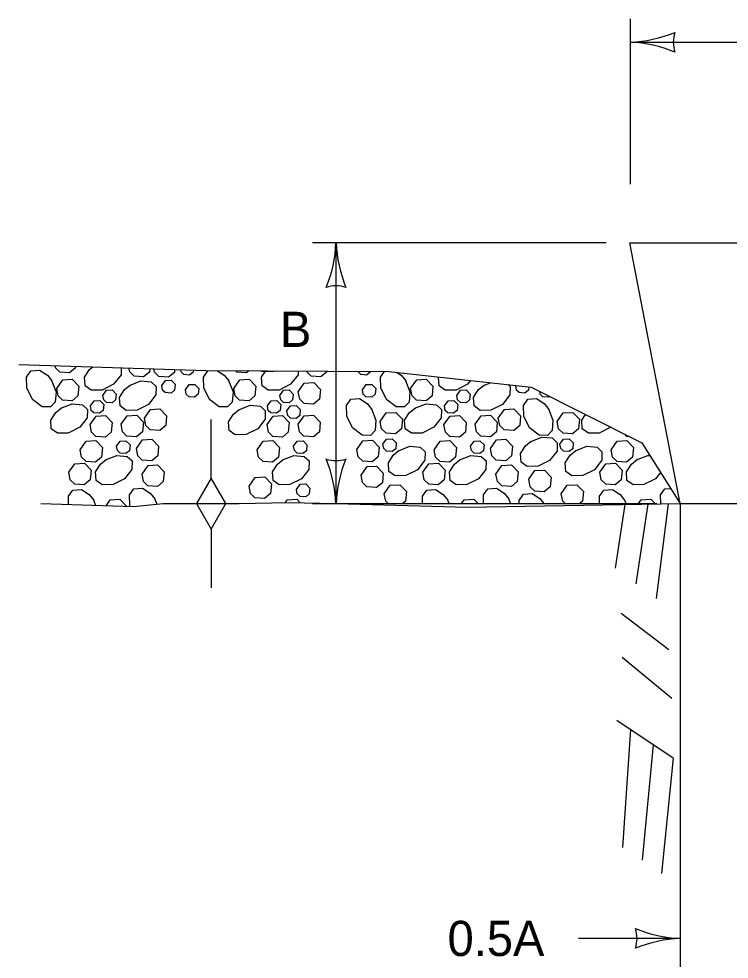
# Model space of a CAD drawing. Extents: x 49991.4 to 50021, y 49987.6 to 50011.4.
# Drawn here: x 50008.562 to 50009.772, y 49996.429 to 49998.032 of the extents above; entities that cross this region are included whole.
import ezdxf

# ---------------------------------------------------------------- set-up
doc = ezdxf.new("R2010")
doc.units = 0
for name, color, linetype in [('Level 1', 7, 'Continuous'), ('Level 2', 7, 'Continuous'), ('Level 3', 7, 'Continuous')]:
    doc.layers.add(name, color=color, linetype=linetype)

msp = doc.modelspace()

# ---------------------------------------------------------------- linework, layer by layer
at = {"layer": 'Level 1'}
for p, q in [((50009.6885, 49997.2058), (50009.6025, 49997.6503)), ((50009.6034, 49997.6503), (50010.4318, 49997.6503)), ((50009.6425, 49997.6503), (50010.4321, 49997.6503)), ((50009.3536, 49997.4073), (50009.3652, 49997.4119)), ((50009.4084, 49997.407), (50009.4084, 49997.4071)), ((50008.8892, 49997.2491), (50008.8892, 49997.3491)), ((50008.8892, 49997.2491), (50008.8642, 49997.2058)), ((50008.9142, 49997.2058), (50008.8892, 49997.2491)), ((50008.6888, 49997.2123), (50008.6925, 49997.2029)), ((50008.7929, 49997.2148), (50008.7969, 49997.2047)), ((50008.8648, 49997.2047), (50008.8892, 49997.1625)), ((50008.8892, 49997.1625), (50008.9142, 49997.2058)), ((50009.0622, 49997.2058), (50009.6485, 49997.2058)), ((50009.2919, 49997.2123), (50009.2945, 49997.2058)), ((50009.396, 49997.2148), (50009.3996, 49997.2058)), ((50009.5945, 49997.2043), (50009.578, 49997.0956)), ((50009.5934, 49997.2123), (50009.596, 49997.2058)), ((50009.6334, 49997.2049), (50009.6128, 49997.0692)), ((50009.668, 49997.2055), (50009.6475, 49997.0442)), ((50009.6885, 49997.2058), (50009.6885, 49994.0392)), ((50009.6885, 49997.2058), (50010.3553, 49997.2058)), ((50008.8892, 49997.1625), (50008.8892, 49997.0625)), ((50009.6691, 49996.9565), (50009.5881, 49997.0186)), ((50009.6743, 49996.8736), (50009.5896, 49996.9437)), ((50009.6768, 49996.7719), (50009.5805, 49996.8365)), ((50009.604, 49996.8207), (50009.5902, 49996.62)), ((50009.6427, 49996.7948), (50009.6239, 49996.598)), ((50009.6768, 49996.7719), (50009.6565, 49996.5756))]:
    msp.add_line(p, q, dxfattribs=at)
for points in [[(50008.5617, 49997.443), (50008.881, 49997.4327), (50009.1922, 49997.431), (50009.4347, 49997.4042), (50009.6233, 49997.3093), (50009.6885, 49997.2058)], [(50008.6175, 49997.4157), (50008.6251, 49997.3965), (50008.6236, 49997.3789), (50008.6156, 49997.3705), (50008.6013, 49997.3708), (50008.5851, 49997.3835), (50008.5753, 49997.4031), (50008.575, 49997.4216), (50008.5824, 49997.432), (50008.5971, 49997.433), (50008.6103, 49997.4246), (50008.618, 49997.4149)], [(50008.6582, 49997.4399), (50008.658, 49997.4373), (50008.6479, 49997.4289), (50008.6317, 49997.4301), (50008.6241, 49997.4374), (50008.6234, 49997.441)], [(50008.7361, 49997.4374), (50008.7359, 49997.4254), (50008.7232, 49997.4092), (50008.7036, 49997.3993), (50008.6851, 49997.399), (50008.6747, 49997.4064), (50008.6737, 49997.4212), (50008.6821, 49997.4343), (50008.6879, 49997.4389)], [(50008.7851, 49997.4358), (50008.7845, 49997.4301), (50008.7744, 49997.4217), (50008.7583, 49997.4229), (50008.7507, 49997.4302), (50008.7494, 49997.437)], [(50008.8272, 49997.4344), (50008.8267, 49997.4295), (50008.8166, 49997.4211), (50008.8004, 49997.4222), (50008.7928, 49997.4296), (50008.7917, 49997.4356)], [(50008.8591, 49997.4334), (50008.8588, 49997.4301), (50008.8527, 49997.425), (50008.843, 49997.4258), (50008.8384, 49997.4302), (50008.8377, 49997.4341)], [(50008.9191, 49997.4157), (50008.9267, 49997.3965), (50008.9251, 49997.3789), (50008.9172, 49997.3705), (50008.9029, 49997.3708), (50008.8867, 49997.3835), (50008.8769, 49997.4031), (50008.8765, 49997.4216), (50008.8839, 49997.432), (50008.893, 49997.4326)], [(50008.8993, 49997.4326), (50008.9118, 49997.4246), (50008.9196, 49997.4149)], [(50008.9535, 49997.4323), (50008.9494, 49997.4289), (50008.9333, 49997.4301), (50008.9309, 49997.4324)], [(50008.9738, 49997.4322), (50008.9757, 49997.4318), (50008.9816, 49997.4318), (50008.99, 49997.4314), (50008.9961, 49997.4314), (50009.0011, 49997.432)], [(50009.0376, 49997.4318), (50009.0375, 49997.4254), (50009.0248, 49997.4092), (50009.0051, 49997.3993), (50008.9867, 49997.399), (50008.9762, 49997.4064), (50008.9753, 49997.4212), (50008.9823, 49997.4321)], [(50009.0862, 49997.4316), (50009.0861, 49997.4301), (50009.076, 49997.4217), (50009.0598, 49997.4229), (50009.0522, 49997.4302), (50009.0519, 49997.4318)], [(50009.1604, 49997.4312), (50009.1603, 49997.4301), (50009.1543, 49997.425), (50009.1446, 49997.4258), (50009.14, 49997.4302), (50009.1398, 49997.4313)], [(50009.2206, 49997.4157), (50009.2282, 49997.3965), (50009.2267, 49997.3789), (50009.2187, 49997.3705), (50009.2045, 49997.3708), (50009.1882, 49997.3835), (50009.1784, 49997.4031), (50009.1781, 49997.4216), (50009.1848, 49997.4311)], [(50009.2056, 49997.4295), (50009.2134, 49997.4246), (50009.2211, 49997.4149)], [(50008.6262, 49997.4022), (50008.6365, 49997.4167), (50008.6528, 49997.4177), (50008.6642, 49997.4059), (50008.6625, 49997.3894), (50008.6524, 49997.381), (50008.6363, 49997.3821), (50008.6287, 49997.3895), (50008.6262, 49997.4022)], [(50008.7505, 49997.4073), (50008.7697, 49997.4149), (50008.7873, 49997.4134), (50008.7957, 49997.4054), (50008.7954, 49997.3912), (50008.7827, 49997.3749), (50008.7631, 49997.3651), (50008.7446, 49997.3648), (50008.7341, 49997.3722), (50008.7332, 49997.3869), (50008.7416, 49997.4001), (50008.7513, 49997.4078)], [(50008.8052, 49997.407), (50008.8114, 49997.4158), (50008.8212, 49997.4163), (50008.828, 49997.4093), (50008.827, 49997.3993), (50008.821, 49997.3943), (50008.8113, 49997.395), (50008.8067, 49997.3994), (50008.8053, 49997.407)], [(50008.9278, 49997.4022), (50008.938, 49997.4167), (50008.9544, 49997.4177), (50008.9657, 49997.4059), (50008.9641, 49997.3894), (50008.954, 49997.381), (50008.9378, 49997.3821), (50008.9302, 49997.3895), (50008.9278, 49997.4022)], [(50009.0378, 49997.3966), (50009.0481, 49997.4112), (50009.0644, 49997.4121), (50009.0758, 49997.4003), (50009.0741, 49997.3838), (50009.064, 49997.3754), (50009.0479, 49997.3765), (50009.0403, 49997.3839), (50009.0378, 49997.3966)], [(50009.2293, 49997.4022), (50009.2396, 49997.4167), (50009.2559, 49997.4177), (50009.2673, 49997.4059), (50009.2657, 49997.3894), (50009.2556, 49997.381), (50009.2394, 49997.3821), (50009.2318, 49997.3895), (50009.2293, 49997.4022)], [(50009.3314, 49997.4156), (50009.3263, 49997.4092), (50009.3067, 49997.3993), (50009.2882, 49997.399), (50009.2778, 49997.4064), (50009.2768, 49997.4212), (50009.2771, 49997.4216)], [(50008.7048, 49997.3902), (50008.711, 49997.399), (50008.7208, 49997.3995), (50008.7276, 49997.3924), (50008.7266, 49997.3825), (50008.7206, 49997.3775), (50008.7109, 49997.3782), (50008.7063, 49997.3826), (50008.7048, 49997.3902)], [(50008.8456, 49997.3998), (50008.8518, 49997.4086), (50008.8616, 49997.4091), (50008.8684, 49997.402), (50008.8674, 49997.3921), (50008.8613, 49997.3871), (50008.8517, 49997.3878), (50008.8471, 49997.3922), (50008.8456, 49997.3998)], [(50009.0064, 49997.3902), (50009.0125, 49997.399), (50009.0224, 49997.3995), (50009.0292, 49997.3924), (50009.0282, 49997.3825), (50009.0221, 49997.3775), (50009.0124, 49997.3782), (50009.0079, 49997.3826), (50009.0064, 49997.3902)], [(50009.1472, 49997.3998), (50009.1533, 49997.4086), (50009.1631, 49997.4091), (50009.1699, 49997.402), (50009.169, 49997.3921), (50009.1629, 49997.3871), (50009.1532, 49997.3878), (50009.1486, 49997.3922), (50009.1472, 49997.3998)], [(50009.3079, 49997.3902), (50009.3141, 49997.399), (50009.3239, 49997.3995), (50009.3307, 49997.3924), (50009.3297, 49997.3825), (50009.3237, 49997.3775), (50009.314, 49997.3782), (50009.3094, 49997.3826), (50009.308, 49997.3902)], [(50009.3955, 49997.4086), (50009.3988, 49997.4054), (50009.3985, 49997.3912), (50009.3858, 49997.3749), (50009.3662, 49997.3651), (50009.3477, 49997.3648), (50009.3373, 49997.3722), (50009.3363, 49997.3869), (50009.3447, 49997.4001), (50009.3544, 49997.4078)], [(50009.4307, 49997.4047), (50009.4302, 49997.3993), (50009.4241, 49997.3943), (50009.4144, 49997.395), (50009.4098, 49997.3994), (50009.4084, 49997.407)], [(50009.4661, 49997.3884), (50009.4645, 49997.3871), (50009.4548, 49997.3878), (50009.4502, 49997.3922), (50009.4493, 49997.3969)], [(50008.6837, 49997.3724), (50008.6899, 49997.3812), (50008.6997, 49997.3817), (50008.7065, 49997.3747), (50008.7055, 49997.3648), (50008.6994, 49997.3597), (50008.6897, 49997.3604), (50008.6852, 49997.3648), (50008.6837, 49997.3724)], [(50008.9853, 49997.3724), (50008.9914, 49997.3812), (50009.0012, 49997.3817), (50009.008, 49997.3747), (50009.0071, 49997.3648), (50009.001, 49997.3597), (50008.9913, 49997.3604), (50008.9867, 49997.3648), (50008.9853, 49997.3724)], [(50009.1626, 49997.3673), (50009.1702, 49997.3481), (50009.1687, 49997.3305), (50009.1608, 49997.3222), (50009.1465, 49997.3224), (50009.1302, 49997.3351), (50009.1204, 49997.3548), (50009.1201, 49997.3733), (50009.1275, 49997.3837), (50009.1422, 49997.3847), (50009.1554, 49997.3762), (50009.1631, 49997.3665)], [(50009.2868, 49997.3724), (50009.293, 49997.3812), (50009.3028, 49997.3817), (50009.3096, 49997.3747), (50009.3086, 49997.3648), (50009.3025, 49997.3597), (50009.2929, 49997.3604), (50009.2883, 49997.3648), (50009.2868, 49997.3724)], [(50009.4642, 49997.3673), (50009.4718, 49997.3481), (50009.4703, 49997.3305), (50009.4623, 49997.3222), (50009.448, 49997.3224), (50009.4318, 49997.3351), (50009.422, 49997.3548), (50009.4217, 49997.3733), (50009.4291, 49997.3837), (50009.4438, 49997.3847), (50009.457, 49997.3762), (50009.4647, 49997.3665)], [(50008.6334, 49997.3683), (50008.6526, 49997.3759), (50008.6702, 49997.3744), (50008.6785, 49997.3664), (50008.6783, 49997.3521), (50008.6656, 49997.3359), (50008.6459, 49997.3261), (50008.6274, 49997.3257), (50008.617, 49997.3331), (50008.616, 49997.3479), (50008.6245, 49997.361), (50008.6342, 49997.3688)], [(50008.7756, 49997.3517), (50008.7859, 49997.3663), (50008.8022, 49997.3672), (50008.8136, 49997.3554), (50008.8119, 49997.3389), (50008.8018, 49997.3305), (50008.7857, 49997.3317), (50008.7781, 49997.339), (50008.7756, 49997.3517)], [(50008.9365, 49997.3658), (50008.9557, 49997.3734), (50008.9733, 49997.3718), (50008.9816, 49997.3639), (50008.9814, 49997.3496), (50008.9687, 49997.3334), (50008.949, 49997.3235), (50008.9305, 49997.3232), (50008.9201, 49997.3306), (50008.9191, 49997.3453), (50008.9276, 49997.3585), (50008.9373, 49997.3662)], [(50009.0185, 49997.3637), (50009.0246, 49997.3725), (50009.0345, 49997.3731), (50009.0413, 49997.366), (50009.0403, 49997.3561), (50009.0342, 49997.351), (50009.0245, 49997.3517), (50009.02, 49997.3561), (50009.0185, 49997.3637)], [(50009.2365, 49997.3683), (50009.2557, 49997.3759), (50009.2733, 49997.3744), (50009.2816, 49997.3664), (50009.2814, 49997.3521), (50009.2687, 49997.3359), (50009.249, 49997.3261), (50009.2305, 49997.3257), (50009.2201, 49997.3331), (50009.2191, 49997.3479), (50009.2276, 49997.361), (50009.2373, 49997.3688)], [(50009.3787, 49997.3517), (50009.389, 49997.3663), (50009.4053, 49997.3672), (50009.4167, 49997.3554), (50009.4151, 49997.3389), (50009.4049, 49997.3305), (50009.3888, 49997.3317), (50009.3812, 49997.339), (50009.3787, 49997.3517)], [(50008.683, 49997.3404), (50008.6933, 49997.355), (50008.7096, 49997.3559), (50008.721, 49997.3441), (50008.7193, 49997.3276), (50008.7092, 49997.3192), (50008.6931, 49997.3204), (50008.6855, 49997.3277), (50008.683, 49997.3404)], [(50008.7359, 49997.341), (50008.7461, 49997.3556), (50008.7625, 49997.3565), (50008.7739, 49997.3447), (50008.7722, 49997.3282), (50008.7621, 49997.3198), (50008.7459, 49997.321), (50008.7384, 49997.3283), (50008.7359, 49997.341)], [(50008.9846, 49997.3404), (50008.9948, 49997.355), (50009.0112, 49997.3559), (50009.0225, 49997.3441), (50009.0209, 49997.3276), (50009.0108, 49997.3192), (50008.9946, 49997.3204), (50008.987, 49997.3277), (50008.9846, 49997.3404)], [(50009.0374, 49997.341), (50009.0477, 49997.3556), (50009.064, 49997.3565), (50009.0754, 49997.3447), (50009.0738, 49997.3282), (50009.0637, 49997.3198), (50009.0475, 49997.321), (50009.0399, 49997.3283), (50009.0374, 49997.341)], [(50009.1774, 49997.3458), (50009.1877, 49997.3604), (50009.204, 49997.3613), (50009.2154, 49997.3495), (50009.2137, 49997.333), (50009.2036, 49997.3246), (50009.1875, 49997.3258), (50009.1799, 49997.3331), (50009.1774, 49997.3458)], [(50009.2861, 49997.3404), (50009.2964, 49997.355), (50009.3127, 49997.3559), (50009.3241, 49997.3441), (50009.3225, 49997.3276), (50009.3124, 49997.3192), (50009.2962, 49997.3204), (50009.2886, 49997.3277), (50009.2861, 49997.3404)], [(50009.339, 49997.341), (50009.3492, 49997.3556), (50009.3656, 49997.3565), (50009.377, 49997.3447), (50009.3753, 49997.3282), (50009.3652, 49997.3198), (50009.3491, 49997.321), (50009.3415, 49997.3283), (50009.339, 49997.341)], [(50009.479, 49997.3458), (50009.4892, 49997.3604), (50009.5056, 49997.3613), (50009.5169, 49997.3495), (50009.5153, 49997.333), (50009.5052, 49997.3246), (50009.489, 49997.3258), (50009.4814, 49997.3331), (50009.479, 49997.3458)], [(50009.5703, 49997.336), (50009.5702, 49997.3359), (50009.5506, 49997.3261), (50009.5321, 49997.3257), (50009.5217, 49997.3331), (50009.5207, 49997.3479), (50009.527, 49997.3577)], [(50009.1821, 49997.3071), (50009.1882, 49997.3158), (50009.198, 49997.3164), (50009.2049, 49997.3093), (50009.2039, 49997.2994), (50009.1978, 49997.2944), (50009.1881, 49997.2951), (50009.1836, 49997.2995), (50009.1821, 49997.3071)], [(50009.4338, 49997.3116), (50009.453, 49997.3192), (50009.4706, 49997.3177), (50009.479, 49997.3097), (50009.4787, 49997.2954), (50009.466, 49997.2792), (50009.4464, 49997.2694), (50009.4279, 49997.2691), (50009.4175, 49997.2765), (50009.4165, 49997.2912), (50009.4249, 49997.3044), (50009.4346, 49997.3121)], [(50009.4836, 49997.3071), (50009.4898, 49997.3158), (50009.4996, 49997.3164), (50009.5064, 49997.3093), (50009.5054, 49997.2994), (50009.4994, 49997.2944), (50009.4897, 49997.2951), (50009.4851, 49997.2995), (50009.4836, 49997.3071)], [(50009.6018, 49997.3201), (50009.5978, 49997.3204), (50009.594, 49997.324)], [(50008.6662, 49997.2977), (50008.6765, 49997.3123), (50008.6928, 49997.3132), (50008.7042, 49997.3014), (50008.7025, 49997.2849), (50008.6924, 49997.2765), (50008.6763, 49997.2777), (50008.6687, 49997.2851), (50008.6662, 49997.2977)], [(50008.7284, 49997.3037), (50008.7345, 49997.3125), (50008.7443, 49997.313), (50008.7512, 49997.3059), (50008.7502, 49997.296), (50008.7441, 49997.291), (50008.7344, 49997.2917), (50008.7299, 49997.2961), (50008.7284, 49997.3037)], [(50008.762, 49997.2999), (50008.7722, 49997.3145), (50008.7886, 49997.3155), (50008.7999, 49997.3037), (50008.7983, 49997.2871), (50008.7882, 49997.2787), (50008.772, 49997.2799), (50008.7644, 49997.2873), (50008.762, 49997.2999)], [(50008.9678, 49997.2977), (50008.978, 49997.3123), (50008.9944, 49997.3132), (50009.0057, 49997.3014), (50009.0041, 49997.2849), (50008.994, 49997.2765), (50008.9778, 49997.2777), (50008.9702, 49997.2851), (50008.9678, 49997.2977)], [(50009.0299, 49997.3037), (50009.0361, 49997.3125), (50009.0459, 49997.313), (50009.0527, 49997.3059), (50009.0517, 49997.296), (50009.0457, 49997.291), (50009.036, 49997.2917), (50009.0314, 49997.2961), (50009.0299, 49997.3037)], [(50009.1376, 49997.2983), (50009.1479, 49997.3129), (50009.1642, 49997.3138), (50009.1756, 49997.302), (50009.174, 49997.2855), (50009.1639, 49997.2771), (50009.1477, 49997.2783), (50009.1401, 49997.2856), (50009.1376, 49997.2983)], [(50009.2086, 49997.2959), (50009.2278, 49997.3035), (50009.2454, 49997.3019), (50009.2538, 49997.294), (50009.2535, 49997.2797), (50009.2408, 49997.2635), (50009.2212, 49997.2536), (50009.2027, 49997.2533), (50009.1923, 49997.2607), (50009.1913, 49997.2755), (50009.1997, 49997.2886), (50009.2094, 49997.2964)], [(50009.2693, 49997.2977), (50009.2796, 49997.3123), (50009.2959, 49997.3132), (50009.3073, 49997.3014), (50009.3057, 49997.2849), (50009.2955, 49997.2765), (50009.2794, 49997.2777), (50009.2718, 49997.2851), (50009.2693, 49997.2977)], [(50009.3315, 49997.3037), (50009.3376, 49997.3125), (50009.3474, 49997.313), (50009.3543, 49997.3059), (50009.3533, 49997.296), (50009.3472, 49997.291), (50009.3375, 49997.2917), (50009.333, 49997.2961), (50009.3315, 49997.3037)], [(50009.3651, 49997.2999), (50009.3753, 49997.3145), (50009.3917, 49997.3155), (50009.403, 49997.3037), (50009.4014, 49997.2871), (50009.3913, 49997.2787), (50009.3751, 49997.2799), (50009.3675, 49997.2873), (50009.3651, 49997.2999)], [(50009.5102, 49997.2959), (50009.5293, 49997.3035), (50009.5469, 49997.3019), (50009.5553, 49997.294), (50009.555, 49997.2797), (50009.5423, 49997.2635), (50009.5227, 49997.2536), (50009.5042, 49997.2533), (50009.4938, 49997.2607), (50009.4928, 49997.2755), (50009.5013, 49997.2886), (50009.511, 49997.2964)], [(50009.5709, 49997.2977), (50009.5811, 49997.3123), (50009.5975, 49997.3132), (50009.6089, 49997.3014), (50009.6072, 49997.2849), (50009.5971, 49997.2765), (50009.5809, 49997.2777), (50009.5734, 49997.2851), (50009.5709, 49997.2977)], [(50008.7096, 49997.2804), (50008.7288, 49997.288), (50008.7464, 49997.2864), (50008.7548, 49997.2785), (50008.7545, 49997.2642), (50008.7418, 49997.248), (50008.7222, 49997.2382), (50008.7037, 49997.2378), (50008.6933, 49997.2452), (50008.6923, 49997.26), (50008.7007, 49997.2731), (50008.7104, 49997.2809)], [(50009.0112, 49997.2804), (50009.0304, 49997.288), (50009.048, 49997.2864), (50009.0563, 49997.2785), (50009.0561, 49997.2642), (50009.0434, 49997.248), (50009.0237, 49997.2382), (50009.0052, 49997.2378), (50008.9948, 49997.2452), (50008.9938, 49997.26), (50009.0023, 49997.2731), (50009.012, 49997.2809)], [(50009.3127, 49997.2804), (50009.3319, 49997.288), (50009.3495, 49997.2864), (50009.3579, 49997.2785), (50009.3576, 49997.2642), (50009.3449, 49997.248), (50009.3253, 49997.2382), (50009.3068, 49997.2378), (50009.2964, 49997.2452), (50009.2954, 49997.26), (50009.3038, 49997.2731), (50009.3135, 49997.2809)], [(50009.6143, 49997.2804), (50009.6335, 49997.288), (50009.6369, 49997.2877)], [(50008.6469, 49997.2592), (50008.6572, 49997.2737), (50008.6735, 49997.2747), (50008.6849, 49997.2629), (50008.6833, 49997.2464), (50008.6732, 49997.238), (50008.657, 49997.2391), (50008.6494, 49997.2465), (50008.6469, 49997.2592)], [(50008.7716, 49997.2563), (50008.7818, 49997.2709), (50008.7982, 49997.2718), (50008.8096, 49997.26), (50008.8079, 49997.2435), (50008.7978, 49997.2351), (50008.7817, 49997.2363), (50008.7741, 49997.2436), (50008.7716, 49997.2563)], [(50009.1448, 49997.2543), (50009.155, 49997.2689), (50009.1714, 49997.2698), (50009.1827, 49997.258), (50009.1811, 49997.2415), (50009.171, 49997.2331), (50009.1548, 49997.2343), (50009.1473, 49997.2416), (50009.1448, 49997.2543)], [(50009.25, 49997.2592), (50009.2603, 49997.2737), (50009.2766, 49997.2747), (50009.288, 49997.2629), (50009.2864, 49997.2464), (50009.2763, 49997.238), (50009.2601, 49997.2391), (50009.2525, 49997.2465), (50009.2501, 49997.2592)], [(50009.3747, 49997.2563), (50009.3849, 49997.2709), (50009.4013, 49997.2718), (50009.4127, 49997.26), (50009.411, 49997.2435), (50009.4009, 49997.2351), (50009.3848, 49997.2363), (50009.3772, 49997.2436), (50009.3747, 49997.2563)], [(50009.5516, 49997.2592), (50009.5618, 49997.2737), (50009.5782, 49997.2747), (50009.5896, 49997.2629), (50009.5879, 49997.2464), (50009.5778, 49997.238), (50009.5617, 49997.2391), (50009.5541, 49997.2465), (50009.5516, 49997.2592)], [(50009.655, 49997.2589), (50009.6465, 49997.248), (50009.6268, 49997.2382), (50009.6084, 49997.2378), (50009.5979, 49997.2452), (50009.597, 49997.26), (50009.6054, 49997.2731), (50009.6151, 49997.2809)], [(50009.4307, 49997.2474), (50009.441, 49997.262), (50009.4573, 49997.2629), (50009.4687, 49997.2511), (50009.467, 49997.2346), (50009.4569, 49997.2262), (50009.4408, 49997.2273), (50009.4332, 49997.2347), (50009.4307, 49997.2474)], [(50008.9541, 49997.2358), (50008.9643, 49997.2503), (50008.9807, 49997.2513), (50008.992, 49997.2395), (50008.9904, 49997.223), (50008.9803, 49997.2146), (50008.9641, 49997.2157), (50008.9565, 49997.2231), (50008.9541, 49997.2358)], [(50009.0347, 49997.2301), (50009.0409, 49997.2389), (50009.0507, 49997.2394), (50009.0575, 49997.2324), (50009.0565, 49997.2225), (50009.0505, 49997.2174), (50009.0408, 49997.2181), (50009.0362, 49997.2225), (50009.0347, 49997.2301)], [(50009.1843, 49997.2226), (50009.1946, 49997.2372), (50009.2109, 49997.2381), (50009.2223, 49997.2263), (50009.2207, 49997.2098), (50009.2159, 49997.2058)], [(50009.4859, 49997.2226), (50009.4961, 49997.2372), (50009.5125, 49997.2381), (50009.5239, 49997.2263), (50009.5222, 49997.2098), (50009.5174, 49997.2058)], [(50008.6465, 49997.2043), (50008.6462, 49997.2183), (50008.6536, 49997.2287), (50008.6684, 49997.2297), (50008.6816, 49997.2212), (50008.6893, 49997.2115)], [(50008.7513, 49997.201), (50008.7507, 49997.2022), (50008.7504, 49997.2207), (50008.7578, 49997.2312), (50008.7725, 49997.2321), (50008.7857, 49997.2237), (50008.7934, 49997.214)], [(50009.1911, 49997.2058), (50009.1868, 49997.2099), (50009.1844, 49997.2226)], [(50009.2496, 49997.2058), (50009.2494, 49997.2183), (50009.2568, 49997.2287), (50009.2715, 49997.2297), (50009.2847, 49997.2212), (50009.2924, 49997.2115)], [(50009.3537, 49997.2058), (50009.3535, 49997.2207), (50009.3609, 49997.2312), (50009.3756, 49997.2321), (50009.3888, 49997.2237), (50009.3965, 49997.214)], [(50009.4143, 49997.2058), (50009.4142, 49997.2114), (50009.4216, 49997.2219), (50009.4364, 49997.2228), (50009.4495, 49997.2144), (50009.4564, 49997.2058)], [(50009.4926, 49997.2058), (50009.4884, 49997.2099), (50009.4859, 49997.2226)], [(50009.5511, 49997.2058), (50009.5509, 49997.2183), (50009.5583, 49997.2287), (50009.573, 49997.2297), (50009.5862, 49997.2212), (50009.5939, 49997.2115)], [(50009.6553, 49997.2053), (50009.655, 49997.2207), (50009.6624, 49997.2312), (50009.6721, 49997.2318)], [(50008.599, 49997.2058), (50008.7571, 49997.2008), (50008.8079, 49997.2058), (50008.9371, 49997.2058), (50009.0206, 49997.2079), (50009.1022, 49997.2058), (50009.3255, 49997.2), (50009.6885, 49997.2058)], [(50008.7104, 49997.2023), (50008.7174, 49997.2124), (50008.7338, 49997.2133), (50008.7452, 49997.2015), (50008.7451, 49997.2012)], [(50009.0158, 49997.2078), (50009.019, 49997.2124), (50009.0353, 49997.2133), (50009.0411, 49997.2074)], [(50009.3159, 49997.2058), (50009.3205, 49997.2124), (50009.3369, 49997.2133), (50009.3441, 49997.2058)], [(50009.6175, 49997.2058), (50009.6221, 49997.2124), (50009.6385, 49997.2133), (50009.6457, 49997.2058)]]:
    msp.add_lwpolyline(points, dxfattribs=at)
at = {"layer": 'Level 3'}
for p, q in [((50009.6034, 49998.032), (50009.6034, 49997.7503)), ((50009.6034, 49997.992), (50010.4318, 49997.992)), ((50009.5625, 49997.6503), (50009.0622, 49997.6503)), ((50009.3151, 49997.6503), (50009.0622, 49997.6503)), ((50009.1022, 49997.2058), (50009.1022, 49997.6503)), ((50009.6885, 49996.4649), (50009.5151, 49996.4649))]:
    msp.add_line(p, q, dxfattribs=at)
for centre, radius, start, end in [((50009.5919, 49998.2247), 0.233, 272.8273, 292.0772), ((50009.7316, 49997.992), 0.0548, 162.1388, 197.8612), ((50009.5943, 49997.7699), 0.2223, 67.456, 87.6395), ((50008.88, 49997.6595), 0.2223, 337.456, 357.6395), ((50009.3349, 49997.6618), 0.233, 182.8273, 202.0772), ((50009.1022, 49997.5221), 0.0548, 72.1388, 107.8612), ((50009.1022, 49997.334), 0.0548, 252.1388, 287.8612), ((50008.8694, 49997.1943), 0.233, 2.8273, 22.0772), ((50009.3243, 49997.1967), 0.2223, 157.456, 177.6395), ((50009.6976, 49996.687), 0.2223, 247.456, 267.6395), ((50009.5602, 49996.4649), 0.0548, 342.1388, 17.8612), ((50009.7, 49996.2322), 0.233, 92.8273, 112.0772)]:
    msp.add_arc(centre, radius, start, end, dxfattribs=at)

# ---------------------------------------------------------------- texts
at = {"layer": 'Level 2'}
for s, p in [('B', (50009.0066, 49997.4728)), ('0.5A', (50009.2922, 49996.4349))]:
    msp.add_text(s, height=0.06, dxfattribs=at).set_placement(p)

doc.saveas('drawing.dxf')
